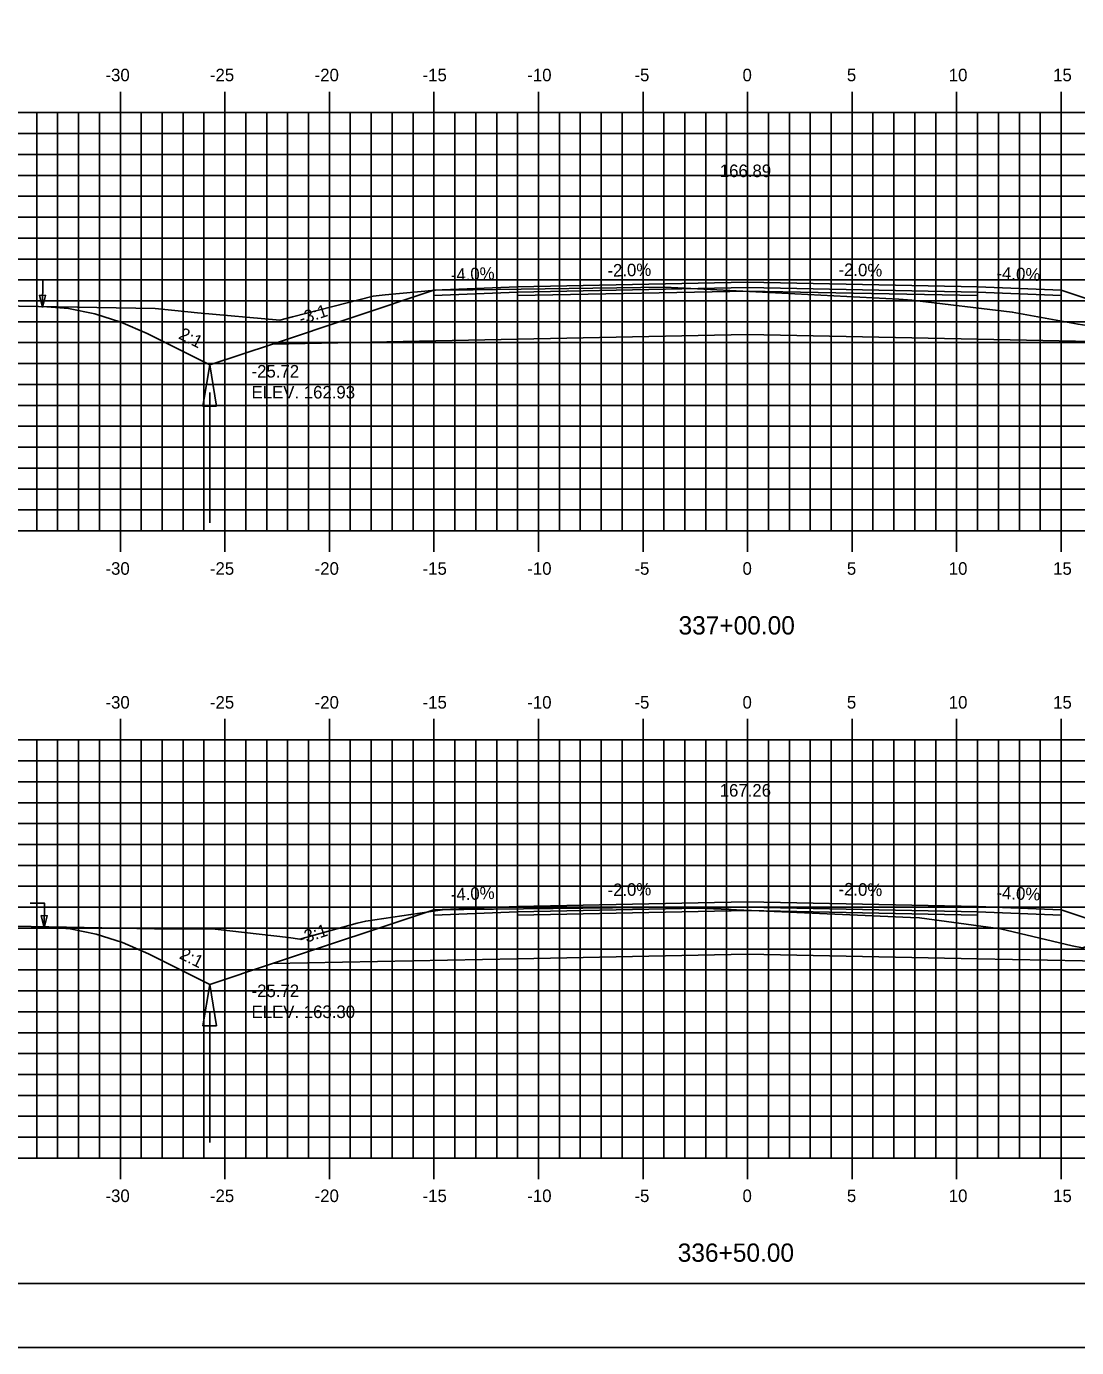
# Model space of a CAD drawing. Extents: x 1142311 to 1142481, y 608981 to 609091.
# Drawn here: x 1142359.8 to 1142410, y 608981.3 to 609044.5 of the extents above; entities that cross this region are included whole.
import ezdxf

# ---------------------------------------------------------------- set-up
doc = ezdxf.new("R2010")
doc.units = 0
for name, color, linetype in [('ANNOTATION', 7, 'Continuous'), ('BORDER', 7, 'Continuous'), ('D_Drainage_Ditch_Line', 7, 'Continuous'), ('D_Roadway_Centerline', 7, 'Continuous'), ('D_Roadway_Centerline_Text', 7, 'Continuous'), ('D_Roadway_Edge_Shoulder', 7, 'Continuous'), ('D_Roadway_Edge_TW', 7, 'Continuous'), ('D_Roadway_Pavement', 7, 'Continuous'), ('D_Roadway_SlopeLines', 7, 'Continuous'), ('D_Roadway_SubGrade', 7, 'Continuous'), ('D_Text_Standard', 7, 'Continuous'), ('H_V ANNOTATION', 7, 'Continuous'), ('MAJOR', 7, 'Continuous'), ('MINOR', 7, 'Continuous'), ('PLOT BOUNDARY', 7, 'Continuous'), ('S_Roadway_Centerline', 7, 'Continuous')]:
    doc.layers.add(name, color=color, linetype=linetype)

msp = doc.modelspace()

# ---------------------------------------------------------------- linework, layer by layer
for points in [[(1142360.574, 609031.058), (1142361.824, 609030.961), (1142363.074, 609030.713), (1142364.324, 609030.314), (1142365.574, 609029.765), (1142368.572, 609028.266), (1142371.572, 609029.266), (1142379.296, 609031.84), (1142379.297, 609031.84), (1142383.297, 609032), (1142394.297, 609032.22), (1142405.297, 609032), (1142409.297, 609031.84), (1142417.02, 609029.266), (1142420.02, 609028.266), (1142422.066, 609029.288), (1142423.316, 609029.835), (1142424.566, 609030.223), (1142425.816, 609030.453), (1142427.066, 609030.525)], [(1142360.646, 609001.398), (1142361.896, 609001.299), (1142363.146, 609001.05), (1142364.396, 609000.65), (1142365.646, 609000.101), (1142368.572, 608998.637), (1142371.572, 608999.637), (1142379.296, 609002.212), (1142379.297, 609002.212), (1142383.297, 609002.372), (1142394.297, 609002.592), (1142405.297, 609002.372), (1142409.297, 609002.212), (1142417.02, 608999.637), (1142420.02, 608998.637), (1142424.006, 609000.63), (1142425.256, 609001.174), (1142426.506, 609001.554), (1142427.756, 609001.772), (1142429.006, 609001.828)]]:
    msp.add_lwpolyline(points)
at = {"layer": 'BORDER'}
msp.add_lwpolyline([(1142319.297, 608984.335), (1142479.297, 608984.335), (1142479.297, 609089.335), (1142319.297, 609089.335)], close=True, dxfattribs=at)
at = {"layer": 'D_Drainage_Ditch_Line'}
for p, q in [((1142368.572, 609026.954), (1142368.572, 609020.71)), ((1142368.572, 608997.325), (1142368.572, 608991.082))]:
    msp.add_line(p, q, dxfattribs=at)
for points in [[(1142368.9, 609026.297), (1142368.244, 609026.297), (1142368.572, 609028.266)], [(1142368.9, 608996.669), (1142368.244, 608996.669), (1142368.572, 608998.637)]]:
    msp.add_lwpolyline(points, close=True, dxfattribs=at)
at = {"layer": 'D_Roadway_Edge_Shoulder'}
for points in [[(1142383.297, 609032), (1142379.297, 609031.84), (1142379.297, 609031.59), (1142383.297, 609031.75)], [(1142405.297, 609032), (1142409.297, 609031.84), (1142409.297, 609031.59), (1142405.297, 609031.75)], [(1142383.297, 609002.372), (1142379.297, 609002.212), (1142379.297, 609001.962), (1142383.297, 609002.122)], [(1142405.297, 609002.372), (1142409.297, 609002.212), (1142409.297, 609001.962), (1142405.297, 609002.122)]]:
    msp.add_lwpolyline(points, close=True, dxfattribs=at)
at = {"layer": 'D_Roadway_Edge_TW'}
for points in [[(1142383.297, 609031.75), (1142383.297, 609032), (1142394.297, 609032.22), (1142405.297, 609032), (1142405.297, 609031.75), (1142394.297, 609031.97)], [(1142383.297, 609002.122), (1142383.297, 609002.372), (1142394.297, 609002.592), (1142405.297, 609002.372), (1142405.297, 609002.122), (1142394.297, 609002.342)]]:
    msp.add_lwpolyline(points, close=True, dxfattribs=at)
at = {"layer": 'D_Roadway_Pavement'}
for points in [[(1142383.297, 609031.584), (1142383.297, 609031.75), (1142394.297, 609031.97), (1142405.297, 609031.75), (1142405.297, 609031.584), (1142394.297, 609031.804)], [(1142383.297, 609001.955), (1142383.297, 609002.122), (1142394.297, 609002.342), (1142405.297, 609002.122), (1142405.297, 609001.955), (1142394.297, 609002.175)]]:
    msp.add_lwpolyline(points, close=True, dxfattribs=at)
at = {"layer": 'D_Roadway_SlopeLines'}
for points in [[(1142368.572, 609028.266), (1142365.574, 609029.765), (1142364.324, 609030.314), (1142363.074, 609030.713), (1142361.824, 609030.961), (1142360.574, 609031.058)], [(1142371.572, 609029.266), (1142368.572, 609028.266)], [(1142368.572, 608998.637), (1142365.646, 609000.101), (1142364.396, 609000.65), (1142363.146, 609001.05), (1142361.896, 609001.299), (1142360.646, 609001.398)], [(1142371.572, 608999.637), (1142368.572, 608998.637)]]:
    msp.add_lwpolyline(points, dxfattribs=at)
at = {"layer": 'D_Roadway_SubGrade'}
for points in [[(1142383.297, 609031.584), (1142383.297, 609031.75), (1142379.297, 609031.59), (1142379.297, 609031.84), (1142379.296, 609031.84), (1142371.572, 609029.266), (1142383.297, 609029.5)], [(1142383.297, 609029.5), (1142383.297, 609031.584), (1142394.297, 609031.804), (1142405.297, 609031.584), (1142405.297, 609029.5), (1142394.297, 609029.72)], [(1142405.297, 609031.584), (1142405.297, 609031.75), (1142409.297, 609031.59), (1142409.297, 609031.84), (1142409.297, 609031.84), (1142417.02, 609029.266), (1142405.297, 609029.5)], [(1142383.297, 609001.955), (1142383.297, 609002.122), (1142379.297, 609001.962), (1142379.297, 609002.212), (1142379.296, 609002.212), (1142371.572, 608999.637), (1142383.297, 608999.872)], [(1142383.297, 608999.872), (1142383.297, 609001.955), (1142394.297, 609002.175), (1142405.297, 609001.955), (1142405.297, 608999.872), (1142394.297, 609000.092)], [(1142405.297, 609001.955), (1142405.297, 609002.122), (1142409.297, 609001.962), (1142409.297, 609002.212), (1142409.297, 609002.212), (1142417.02, 608999.637), (1142405.297, 608999.872)]]:
    msp.add_lwpolyline(points, close=True, dxfattribs=at)
at = {"layer": 'D_Text_Standard'}
for points in [[(1142360.574, 609031.015), (1142360.585, 609032.346), (1142359.905, 609032.346)], [(1142360.646, 609001.351), (1142360.669, 609002.523), (1142359.989, 609002.523)]]:
    msp.add_lwpolyline(points, dxfattribs=at)
for points in [[(1142360.574, 609031.015), (1142360.433, 609031.598), (1142360.724, 609031.596)], [(1142360.646, 609001.351), (1142360.512, 609001.935), (1142360.803, 609001.93)]]:
    msp.add_lwpolyline(points, close=True, dxfattribs=at)
at = {"layer": 'MAJOR'}
for p, q in [((1142364.297, 609041.337), (1142364.297, 609040.335)), ((1142369.297, 609041.337), (1142369.297, 609040.335)), ((1142374.297, 609041.337), (1142374.297, 609040.335)), ((1142379.297, 609041.337), (1142379.297, 609040.335)), ((1142384.297, 609041.337), (1142384.297, 609040.335)), ((1142389.297, 609041.337), (1142389.297, 609040.335)), ((1142394.297, 609041.337), (1142394.297, 609040.335)), ((1142399.297, 609041.337), (1142399.297, 609040.335)), ((1142404.297, 609041.337), (1142404.297, 609040.335)), ((1142409.297, 609041.337), (1142409.297, 609040.335)), ((1142324.297, 609040.335), (1142464.297, 609040.335)), ((1142324.297, 609040.335), (1142464.297, 609040.335)), ((1142364.297, 609020.335), (1142364.297, 609040.335)), ((1142369.297, 609020.335), (1142369.297, 609040.335)), ((1142374.297, 609020.335), (1142374.297, 609040.335)), ((1142379.297, 609020.335), (1142379.297, 609040.335)), ((1142384.297, 609020.335), (1142384.297, 609040.335)), ((1142389.297, 609020.335), (1142389.297, 609040.335)), ((1142394.297, 609020.335), (1142394.297, 609040.335)), ((1142399.297, 609020.335), (1142399.297, 609040.335)), ((1142404.297, 609020.335), (1142404.297, 609040.335)), ((1142409.297, 609020.335), (1142409.297, 609040.335)), ((1142324.297, 609035.335), (1142464.297, 609035.335)), ((1142324.297, 609030.335), (1142464.297, 609030.335)), ((1142324.297, 609025.335), (1142464.297, 609025.335)), ((1142324.297, 609020.335), (1142464.297, 609020.335)), ((1142324.297, 609020.335), (1142464.297, 609020.335)), ((1142364.297, 609019.333), (1142364.297, 609020.335)), ((1142369.297, 609019.333), (1142369.297, 609020.335)), ((1142374.297, 609019.333), (1142374.297, 609020.335)), ((1142379.297, 609019.333), (1142379.297, 609020.335)), ((1142384.297, 609019.333), (1142384.297, 609020.335)), ((1142389.297, 609019.333), (1142389.297, 609020.335)), ((1142394.297, 609019.333), (1142394.297, 609020.335)), ((1142399.297, 609019.333), (1142399.297, 609020.335)), ((1142404.297, 609019.333), (1142404.297, 609020.335)), ((1142409.297, 609019.333), (1142409.297, 609020.335)), ((1142364.297, 609011.337), (1142364.297, 609010.335)), ((1142369.297, 609011.337), (1142369.297, 609010.335)), ((1142374.297, 609011.337), (1142374.297, 609010.335)), ((1142379.297, 609011.337), (1142379.297, 609010.335)), ((1142384.297, 609011.337), (1142384.297, 609010.335)), ((1142389.297, 609011.337), (1142389.297, 609010.335)), ((1142394.297, 609011.337), (1142394.297, 609010.335)), ((1142399.297, 609011.337), (1142399.297, 609010.335)), ((1142404.297, 609011.337), (1142404.297, 609010.335)), ((1142409.297, 609011.337), (1142409.297, 609010.335)), ((1142324.297, 609010.335), (1142464.297, 609010.335)), ((1142324.297, 609010.335), (1142464.297, 609010.335)), ((1142364.297, 608990.335), (1142364.297, 609010.335)), ((1142369.297, 608990.335), (1142369.297, 609010.335)), ((1142374.297, 608990.335), (1142374.297, 609010.335)), ((1142379.297, 608990.335), (1142379.297, 609010.335)), ((1142384.297, 608990.335), (1142384.297, 609010.335)), ((1142389.297, 608990.335), (1142389.297, 609010.335)), ((1142394.297, 608990.335), (1142394.297, 609010.335)), ((1142399.297, 608990.335), (1142399.297, 609010.335)), ((1142404.297, 608990.335), (1142404.297, 609010.335)), ((1142409.297, 608990.335), (1142409.297, 609010.335)), ((1142324.297, 609005.335), (1142464.297, 609005.335)), ((1142324.297, 609000.335), (1142464.297, 609000.335)), ((1142324.297, 608995.335), (1142464.297, 608995.335)), ((1142324.297, 608990.335), (1142464.297, 608990.335)), ((1142324.297, 608990.335), (1142464.297, 608990.335)), ((1142364.297, 608989.333), (1142364.297, 608990.335)), ((1142369.297, 608989.333), (1142369.297, 608990.335)), ((1142374.297, 608989.333), (1142374.297, 608990.335)), ((1142379.297, 608989.333), (1142379.297, 608990.335)), ((1142384.297, 608989.333), (1142384.297, 608990.335)), ((1142389.297, 608989.333), (1142389.297, 608990.335)), ((1142394.297, 608989.333), (1142394.297, 608990.335)), ((1142399.297, 608989.333), (1142399.297, 608990.335)), ((1142404.297, 608989.333), (1142404.297, 608990.335)), ((1142409.297, 608989.333), (1142409.297, 608990.335))]:
    msp.add_line(p, q, dxfattribs=at)
at = {"layer": 'MINOR'}
for p, q in [((1142360.297, 609020.335), (1142360.297, 609040.335)), ((1142361.297, 609020.335), (1142361.297, 609040.335)), ((1142362.297, 609020.335), (1142362.297, 609040.335)), ((1142363.297, 609020.335), (1142363.297, 609040.335)), ((1142365.297, 609020.335), (1142365.297, 609040.335)), ((1142366.297, 609020.335), (1142366.297, 609040.335)), ((1142367.297, 609020.335), (1142367.297, 609040.335)), ((1142368.297, 609020.335), (1142368.297, 609040.335)), ((1142370.297, 609020.335), (1142370.297, 609040.335)), ((1142371.297, 609020.335), (1142371.297, 609040.335)), ((1142372.297, 609020.335), (1142372.297, 609040.335)), ((1142373.297, 609020.335), (1142373.297, 609040.335)), ((1142375.297, 609020.335), (1142375.297, 609040.335)), ((1142376.297, 609020.335), (1142376.297, 609040.335)), ((1142377.297, 609020.335), (1142377.297, 609040.335)), ((1142378.297, 609020.335), (1142378.297, 609040.335)), ((1142380.297, 609020.335), (1142380.297, 609040.335)), ((1142381.297, 609020.335), (1142381.297, 609040.335)), ((1142382.297, 609020.335), (1142382.297, 609040.335)), ((1142383.297, 609020.335), (1142383.297, 609040.335)), ((1142385.297, 609020.335), (1142385.297, 609040.335)), ((1142386.297, 609020.335), (1142386.297, 609040.335)), ((1142387.297, 609020.335), (1142387.297, 609040.335)), ((1142388.297, 609020.335), (1142388.297, 609040.335)), ((1142390.297, 609020.335), (1142390.297, 609040.335)), ((1142391.297, 609020.335), (1142391.297, 609040.335)), ((1142392.297, 609020.335), (1142392.297, 609040.335)), ((1142393.297, 609020.335), (1142393.297, 609040.335)), ((1142395.297, 609020.335), (1142395.297, 609040.335)), ((1142396.297, 609020.335), (1142396.297, 609040.335)), ((1142397.297, 609020.335), (1142397.297, 609040.335)), ((1142398.297, 609020.335), (1142398.297, 609040.335)), ((1142400.297, 609020.335), (1142400.297, 609040.335)), ((1142401.297, 609020.335), (1142401.297, 609040.335)), ((1142402.297, 609020.335), (1142402.297, 609040.335)), ((1142403.297, 609020.335), (1142403.297, 609040.335)), ((1142405.297, 609020.335), (1142405.297, 609040.335)), ((1142406.297, 609020.335), (1142406.297, 609040.335)), ((1142407.297, 609020.335), (1142407.297, 609040.335)), ((1142408.297, 609020.335), (1142408.297, 609040.335)), ((1142324.297, 609039.335), (1142464.297, 609039.335)), ((1142324.297, 609038.335), (1142464.297, 609038.335)), ((1142324.297, 609037.335), (1142464.297, 609037.335)), ((1142324.297, 609036.335), (1142464.297, 609036.335)), ((1142324.297, 609034.335), (1142464.297, 609034.335)), ((1142324.297, 609033.335), (1142464.297, 609033.335)), ((1142324.297, 609032.335), (1142464.297, 609032.335)), ((1142324.297, 609031.335), (1142464.297, 609031.335)), ((1142324.297, 609029.335), (1142464.297, 609029.335)), ((1142324.297, 609028.335), (1142464.297, 609028.335)), ((1142324.297, 609027.335), (1142464.297, 609027.335)), ((1142324.297, 609026.335), (1142464.297, 609026.335)), ((1142324.297, 609024.335), (1142464.297, 609024.335)), ((1142324.297, 609023.335), (1142464.297, 609023.335)), ((1142324.297, 609022.335), (1142464.297, 609022.335)), ((1142324.297, 609021.335), (1142464.297, 609021.335)), ((1142360.297, 608990.335), (1142360.297, 609010.335)), ((1142361.297, 608990.335), (1142361.297, 609010.335)), ((1142362.297, 608990.335), (1142362.297, 609010.335)), ((1142363.297, 608990.335), (1142363.297, 609010.335)), ((1142365.297, 608990.335), (1142365.297, 609010.335)), ((1142366.297, 608990.335), (1142366.297, 609010.335)), ((1142367.297, 608990.335), (1142367.297, 609010.335)), ((1142368.297, 608990.335), (1142368.297, 609010.335)), ((1142370.297, 608990.335), (1142370.297, 609010.335)), ((1142371.297, 608990.335), (1142371.297, 609010.335)), ((1142372.297, 608990.335), (1142372.297, 609010.335)), ((1142373.297, 608990.335), (1142373.297, 609010.335)), ((1142375.297, 608990.335), (1142375.297, 609010.335)), ((1142376.297, 608990.335), (1142376.297, 609010.335)), ((1142377.297, 608990.335), (1142377.297, 609010.335)), ((1142378.297, 608990.335), (1142378.297, 609010.335)), ((1142380.297, 608990.335), (1142380.297, 609010.335)), ((1142381.297, 608990.335), (1142381.297, 609010.335)), ((1142382.297, 608990.335), (1142382.297, 609010.335)), ((1142383.297, 608990.335), (1142383.297, 609010.335)), ((1142385.297, 608990.335), (1142385.297, 609010.335)), ((1142386.297, 608990.335), (1142386.297, 609010.335)), ((1142387.297, 608990.335), (1142387.297, 609010.335)), ((1142388.297, 608990.335), (1142388.297, 609010.335)), ((1142390.297, 608990.335), (1142390.297, 609010.335)), ((1142391.297, 608990.335), (1142391.297, 609010.335)), ((1142392.297, 608990.335), (1142392.297, 609010.335)), ((1142393.297, 608990.335), (1142393.297, 609010.335)), ((1142395.297, 608990.335), (1142395.297, 609010.335)), ((1142396.297, 608990.335), (1142396.297, 609010.335)), ((1142397.297, 608990.335), (1142397.297, 609010.335)), ((1142398.297, 608990.335), (1142398.297, 609010.335)), ((1142400.297, 608990.335), (1142400.297, 609010.335)), ((1142401.297, 608990.335), (1142401.297, 609010.335)), ((1142402.297, 608990.335), (1142402.297, 609010.335)), ((1142403.297, 608990.335), (1142403.297, 609010.335)), ((1142405.297, 608990.335), (1142405.297, 609010.335)), ((1142406.297, 608990.335), (1142406.297, 609010.335)), ((1142407.297, 608990.335), (1142407.297, 609010.335)), ((1142408.297, 608990.335), (1142408.297, 609010.335)), ((1142324.297, 609009.335), (1142464.297, 609009.335)), ((1142324.297, 609008.335), (1142464.297, 609008.335)), ((1142324.297, 609007.335), (1142464.297, 609007.335)), ((1142324.297, 609006.335), (1142464.297, 609006.335)), ((1142324.297, 609004.335), (1142464.297, 609004.335)), ((1142324.297, 609003.335), (1142464.297, 609003.335)), ((1142324.297, 609002.335), (1142464.297, 609002.335)), ((1142324.297, 609001.335), (1142464.297, 609001.335)), ((1142324.297, 608999.335), (1142464.297, 608999.335)), ((1142324.297, 608998.335), (1142464.297, 608998.335)), ((1142324.297, 608997.335), (1142464.297, 608997.335)), ((1142324.297, 608996.335), (1142464.297, 608996.335)), ((1142324.297, 608994.335), (1142464.297, 608994.335)), ((1142324.297, 608993.335), (1142464.297, 608993.335)), ((1142324.297, 608992.335), (1142464.297, 608992.335)), ((1142324.297, 608991.335), (1142464.297, 608991.335))]:
    msp.add_line(p, q, dxfattribs=at)
at = {"layer": 'PLOT BOUNDARY'}
msp.add_lwpolyline([(1142311.204, 608981.276), (1142481.204, 608981.276), (1142481.204, 609091.276), (1142311.204, 609091.276)], close=True, dxfattribs=at)
at = {"layer": 'S_Roadway_Centerline'}
for points in [[(1142324.297, 609031.45), (1142339.038, 609031.267), (1142344.584, 609031.334), (1142365.956, 609030.965), (1142367.521, 609030.805), (1142367.992, 609030.755), (1142371.922, 609030.416), (1142372.533, 609030.575), (1142376.384, 609031.552), (1142376.966, 609031.616), (1142379.377, 609031.848), (1142381.17, 609031.866), (1142390.341, 609031.991), (1142392.202, 609031.893), (1142401.531, 609031.422), (1142402.162, 609031.372), (1142406.958, 609030.794), (1142410.108, 609030.213), (1142410.523, 609030.158), (1142411.1, 609030.269), (1142416.795, 609030.647), (1142419.825, 609030.564), (1142444.36, 609030.432), (1142450.84, 609030.42)], [(1142337.275, 609001.841), (1142365.933, 609001.298), (1142368.833, 609001.283), (1142372.333, 609000.894), (1142372.884, 609000.81), (1142375.622, 609001.579), (1142376.038, 609001.669), (1142379.479, 609002.185), (1142379.698, 609002.212), (1142380.725, 609002.225), (1142390.691, 609002.337), (1142391.949, 609002.296), (1142402.095, 609001.847), (1142402.522, 609001.826), (1142406.399, 609001.303), (1142409.823, 609000.49), (1142410.322, 609000.387), (1142415.334, 609002.008), (1142415.882, 609002.14), (1142421.695, 609001.98), (1142453.493, 609001.317)]]:
    msp.add_lwpolyline(points, dxfattribs=at)

# ---------------------------------------------------------------- texts
at = {"layer": 'ANNOTATION'}
for s, rotation, p in [('-4.0%', 2.29061, (1142380.113, 609032.274)), ('-2.0%', 1.14576, (1142387.6, 609032.487)), ('-2.0%', 358.85424, (1142398.64, 609032.534)), ('-4.0%', 357.70939, (1142406.193, 609032.365)), ('-3:1', 18.43482, (1142372.951, 609030.18)), ('2:1', 333.43495, (1142367.04, 609029.55)), ('-4.0%', 2.29061, (1142380.113, 609002.645)), ('-2.0%', 1.14576, (1142387.6, 609002.858)), ('-2.0%', 358.85424, (1142398.64, 609002.905)), ('-4.0%', 357.70939, (1142406.193, 609002.737)), ('-3:1', 18.43482, (1142372.951, 609000.551)), ('2:1', 333.43495, (1142367.076, 608999.904))]:
    msp.add_text(s, height=0.6, rotation=rotation, dxfattribs=at).set_placement(p)
at = {"layer": 'D_Roadway_Centerline'}
for s, p in [('C', (1142394.292, 609032.22)), ('L', (1142394.297, 609032.213)), ('C', (1142394.292, 609002.592)), ('L', (1142394.297, 609002.585))]:
    msp.add_text(s, height=0.0146, dxfattribs=at).set_placement(p)
at = {"layer": 'D_Roadway_Centerline_Text'}
for s, p in [('166.89', (1142392.97, 609037.252)), ('167.26', (1142392.964, 609007.624))]:
    msp.add_text(s, height=0.6, dxfattribs=at).set_placement(p)
at = {"layer": 'D_Text_Standard'}
for s, p in [('-25.72', (1142370.572, 609027.666)), ('ELEV. 162.93', (1142370.572, 609026.664)), ('-25.72', (1142370.572, 608998.037)), ('ELEV. 163.30', (1142370.572, 608997.035))]:
    msp.add_text(s, height=0.6, dxfattribs=at).set_placement(p)
at = {"layer": 'H_V ANNOTATION'}
for s, height, p in [('-30', 0.6, (1142363.585, 609041.835)), ('-25', 0.6, (1142368.582, 609041.835)), ('-20', 0.6, (1142373.59, 609041.835)), ('-15', 0.6, (1142378.754, 609041.835)), ('-10', 0.6, (1142383.762, 609041.835)), ('-5', 0.6, (1142388.887, 609041.835)), ('0', 0.6, (1142394.056, 609041.835)), ('5', 0.6, (1142399.048, 609041.835)), ('10', 0.6, (1142403.922, 609041.835)), ('15', 0.6, (1142408.914, 609041.835)), ('-30', 0.6, (1142363.585, 609018.235)), ('-25', 0.6, (1142368.582, 609018.235)), ('-20', 0.6, (1142373.59, 609018.235)), ('-15', 0.6, (1142378.754, 609018.235)), ('-10', 0.6, (1142383.762, 609018.235)), ('-5', 0.6, (1142388.887, 609018.235)), ('0', 0.6, (1142394.056, 609018.235)), ('5', 0.6, (1142399.048, 609018.235)), ('10', 0.6, (1142403.922, 609018.235)), ('15', 0.6, (1142408.914, 609018.235)), ('337+00.00', 0.875, (1142390.996, 609015.378)), ('-30', 0.6, (1142363.585, 609011.835)), ('-25', 0.6, (1142368.582, 609011.835)), ('-20', 0.6, (1142373.59, 609011.835)), ('-15', 0.6, (1142378.754, 609011.835)), ('-10', 0.6, (1142383.762, 609011.835)), ('-5', 0.6, (1142388.887, 609011.835)), ('0', 0.6, (1142394.056, 609011.835)), ('5', 0.6, (1142399.048, 609011.835)), ('10', 0.6, (1142403.922, 609011.835)), ('15', 0.6, (1142408.914, 609011.835)), ('-30', 0.6, (1142363.585, 608988.235)), ('-25', 0.6, (1142368.582, 608988.235)), ('-20', 0.6, (1142373.59, 608988.235)), ('-15', 0.6, (1142378.754, 608988.235)), ('-10', 0.6, (1142383.762, 608988.235)), ('-5', 0.6, (1142388.887, 608988.235)), ('0', 0.6, (1142394.056, 608988.235)), ('5', 0.6, (1142399.048, 608988.235)), ('10', 0.6, (1142403.922, 608988.235)), ('15', 0.6, (1142408.914, 608988.235)), ('336+50.00', 0.875, (1142390.957, 608985.378))]:
    msp.add_text(s, height=height, dxfattribs=at).set_placement(p)
at = {"layer": 'S_Roadway_Centerline'}
for s, p in [('L', (1142390.333, 609031.983)), ('C', (1142390.336, 609031.991)), ('L', (1142390.683, 609002.329)), ('C', (1142390.686, 609002.337))]:
    msp.add_text(s, height=0.0146, dxfattribs=at).set_placement(p)

doc.saveas('drawing.dxf')
